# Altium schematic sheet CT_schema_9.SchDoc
size 278 x 170 mm
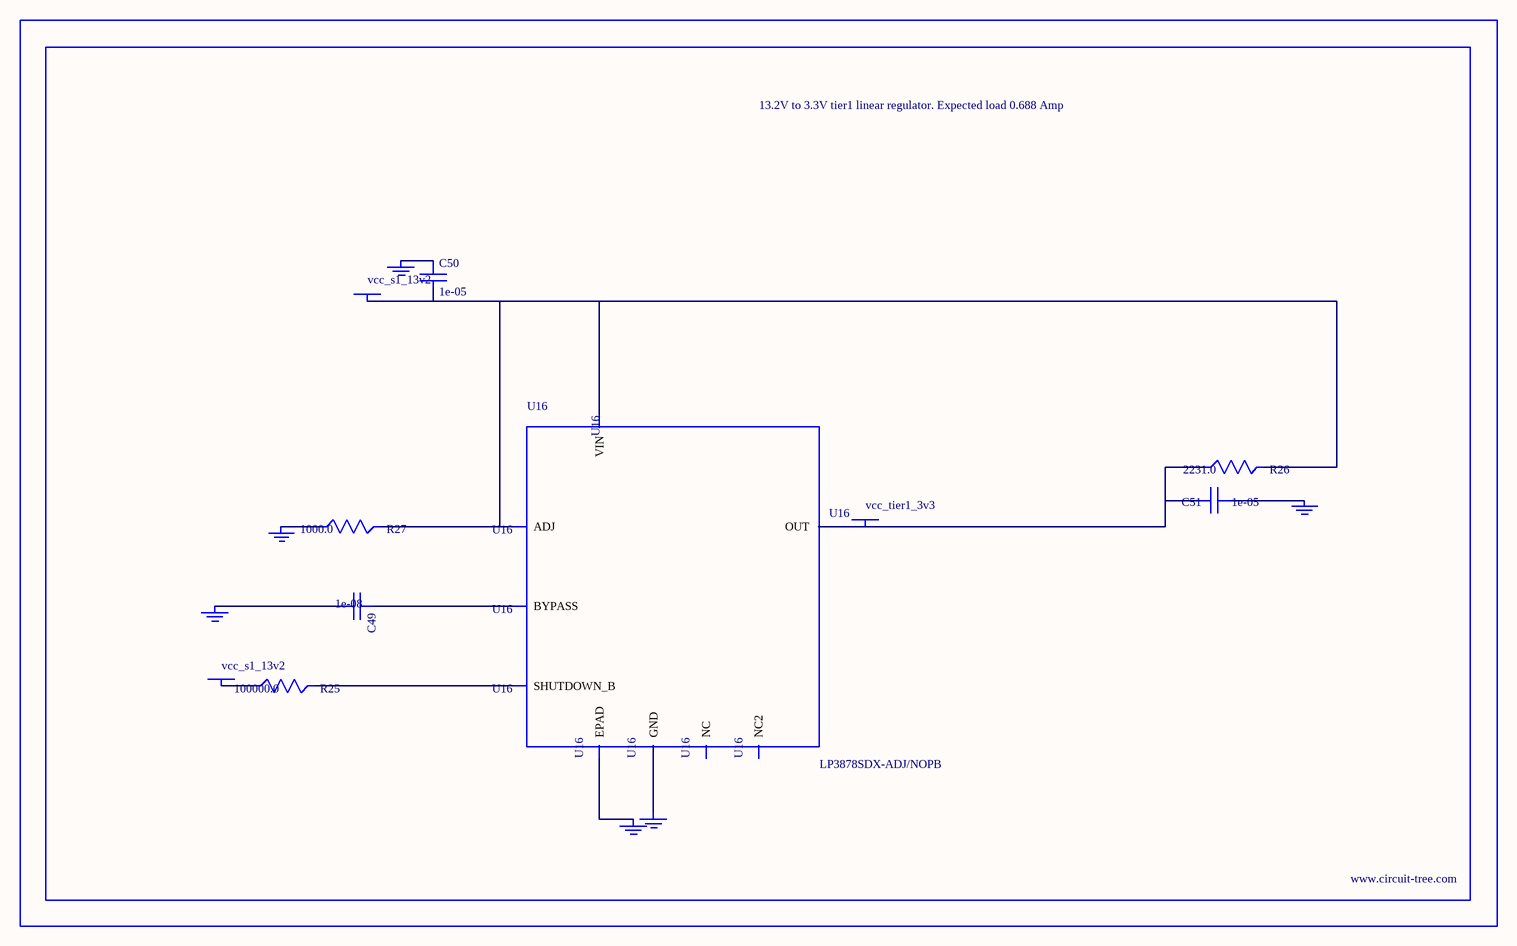
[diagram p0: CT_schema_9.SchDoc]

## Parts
BORDER8  (no value)
C49  1e-08  [C0402]
C50  1e-05  [C1210]
C51  1e-05  [C1210]
GND_INSTANCE_8_0  (no value)
GND_INSTANCE_8_1  (no value)
GND_INSTANCE_8_2  (no value)
GND_INSTANCE_8_3  (no value)
GND_INSTANCE_8_4  (no value)
GND_INSTANCE_8_5  (no value)
POWER_INSTANCE_8_0  vcc_s1_13v2
POWER_INSTANCE_8_1  vcc_s1_13v2
POWER_INSTANCE_8_2  vcc_tier1_3v3
R25  100000.0  [R0603]
R26  2231.0  [R0603]
R27  1000.0  [R0603]
U16  LP3878SDX-ADJ/NOPB  [WSON-8]

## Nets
NetC49_1: C49.1 U16.1(BYPASS)
NetC49_2: C49.2 GND_INSTANCE_8_0.0(GND)
NetC50_1: C50.1 GND_INSTANCE_8_1.0(GND)
NetC50_2: C50.2 POWER_INSTANCE_8_0.0(PWR) R26.2 R27.2 U16.4(VIN) U16.6(ADJ)
NetC51_1: C51.1 GND_INSTANCE_8_2.0(GND)
NetC51_2: C51.2 POWER_INSTANCE_8_2.0(PWR) R26.1 U16.5(OUT)
NetGND_INSTANCE_8_3_0: GND_INSTANCE_8_3.0(GND) R27.1
NetGND_INSTANCE_8_4_0: GND_INSTANCE_8_4.0(GND) U16.PAD(EPAD)
NetGND_INSTANCE_8_5_0: GND_INSTANCE_8_5.0(GND) U16.3(GND)
NetPOWER_INSTANCE_8_1_0: POWER_INSTANCE_8_1.0(PWR) R25.1
NetR25_2: R25.2 U16.8(SHUTDOWN_B)

Not connected (* = marked no-connect by the designer): U16 2(NC) 7(NC2)

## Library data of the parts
BORDER8 = BORDER_PAGE8
C49 = C0402C103K3RAC
C50 = C1210C106K5PACTU
C51 = GRM32DR61E106MA12L
GND_INSTANCE_8_0-GND_INSTANCE_8_5 = GND
POWER_INSTANCE_8_0-POWER_INSTANCE_8_2 = PWR
R25 = RC0603JR-07100KL
R26 = R26
R27 = RC0603JR-071KL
